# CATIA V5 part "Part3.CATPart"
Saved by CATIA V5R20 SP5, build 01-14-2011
Part number: 中
Bounding box of the stored display mesh (mm): x -15 to 15, y -20 to 20, z -30 to 90
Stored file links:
  F:\CAD\很靠后、\Part3.CATPart
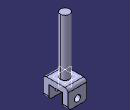
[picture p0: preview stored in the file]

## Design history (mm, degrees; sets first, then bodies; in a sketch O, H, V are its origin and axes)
Body1 (main body)
  Sketch1 on xy-plane, origin (0, 0, 0), H (1, 0, 0), V (0, 1, 0)
    circle A1 centre (0, 0) radius 7.5
    radius A1 = 7.5
  Pad1: profile Sketch1, direction (0, 0, 1), length 90
  Sketch2 on zx-plane, origin (0, 0, 0), H (-1, 0, 0), V (0, 0, 1)
    point P1 (-15, 0)
    line L1 (-15, 0) -> (15, 0)
    line L2 (15, 0) -> (15, -30)
    line L3 (15, -30) -> (-15, -30)
    line L4 (-15, -30) -> (-15, 0)
    length L1 = 30
    distance O P1 = 15
    length L2 = 30
    coincidence: P1 H
    horizontal: L1 H, L3 H
    vertical: L2 V, L4 V
  Pad2: profile Sketch2, direction (0, 1, 0), length 20, mirrored extent
  Sketch3 on yz-plane, origin (0, 0, 0), H (0, 1, 0), V (0, 0, 1)
    line L1 (-11, -9) -> (11, -9)
    line L2 (11, -9) -> (11, -34)
    line L3 (11, -34) -> (-11, -34)
    line L4 (-11, -34) -> (-11, -9)
    length L1 = 22
    length L2 = 25
    distance O L2 = 11
    distance O L1 = 9
    horizontal: L1 H, L3 H
    vertical: L2 V, L4 V
  Pocket1: profile Sketch3, direction (-1, 0, 0), length 20, mirrored extent
  Sketch4 on start face of Pad2, origin (0, -20, 0), H (1, 0, 0), V (0, 0, 1)
    circle A1 centre (0, -20) radius 5
    point P1 (0, -20)
    reference projected line E1 (15, -30) -> (-15, -30) from edge [start face of Pad2 | face of Pad2 from Sketch2.L3]
    radius A1 = 5
    distance P1 E1 = 10
    coincidence: P1 V
  Pocket2: profile Sketch4, direction (0, 1, 0), length 40
  Fillet1: radius 5, on edge [face of Pad2 from Sketch2.L1 | end face of Pad2]
  Fillet2: radius 5, on edge [start face of Pad2 | face of Pad2 from Sketch2.L1]
  Fillet3: radius 5, on edge [face of Pad2 from Sketch2.L3 | face of Pad2 from Sketch2.L4] (x2); edge [face of Pad2 from Sketch2.L2 | face of Pad2 from Sketch2.L3] (x2)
